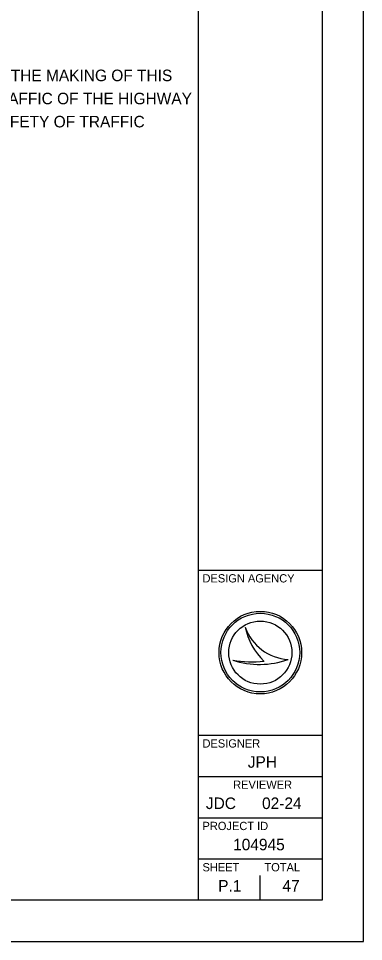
# Model space of a CAD drawing. Extents: x 6.3 to 40.3, y 9 to 31.
# Drawn here: x 36.17 to 40.34, y 9.05 to 20.23 of the extents above; entities that cross this region are included whole.
import ezdxf

# ---------------------------------------------------------------- set-up
doc = ezdxf.new("R2010")
doc.units = 0
for name, color, linetype in [('SH_Border', 7, 'Continuous'), ('SH_Cut_Line', 7, 'Continuous'), ('SH_Data', 7, 'Continuous')]:
    doc.layers.add(name, color=color, linetype=linetype)

msp = doc.modelspace()

# ---------------------------------------------------------------- linework, layer by layer
at = {"layer": 'SH_Border'}
for p, q in [((38.345, 9.546), (38.345, 30.546)), ((38.345, 13.546), (39.845, 13.546)), ((38.345, 11.546), (39.845, 11.546)), ((38.345, 11.046), (39.845, 11.046)), ((38.345, 10.546), (39.845, 10.546)), ((38.345, 10.046), (39.845, 10.046))]:
    msp.add_line(p, q, dxfattribs=at)
msp.add_lwpolyline([(7.845, 30.546), (39.845, 30.546), (39.845, 9.546), (7.845, 9.546)], close=True, dxfattribs=at)
at = {"layer": 'SH_Cut_Line'}
msp.add_lwpolyline([(6.345, 9.046), (40.345, 9.046), (40.345, 31.046), (6.345, 31.046)], close=True, dxfattribs=at)
at = {"layer": 'SH_Data'}
for p, q in [((38.912, 12.855), (38.912, 12.855)), ((39.095, 12.546), (39.095, 12.546)), ((38.762, 12.455), (38.762, 12.455)), ((39.432, 12.464), (39.432, 12.464)), ((39.095, 9.546), (39.095, 9.846)), ((38.72, 9.721), (38.72, 9.721))]:
    msp.add_line(p, q, dxfattribs=at)
for radius in [0.5, 0.477, 0.477, 0.382]:
    msp.add_circle((39.095, 12.546), radius, dxfattribs=at)
for centre, radius, start, end in [((39.461, 13.043), 0.58, 198.9257, 198.9319), ((39.691, 13.016), 0.796, 191.6379, 191.6421), ((39.461, 13.043), 0.58, 198.9319, 267.1657), ((39.691, 13.016), 0.796, 191.6421, 226.0947), ((39.084, 13.416), 1.013, 251.4576, 290.0832), ((38.993, 13.7), 1.266, 259.4964, 259.4995), ((39.084, 13.416), 1.013, 251.4527, 251.4576), ((38.993, 13.7), 1.266, 259.4995, 276.6672)]:
    msp.add_arc(centre, radius, start, end, dxfattribs=at)

# ---------------------------------------------------------------- texts
for s, height, p in [(' I HEREBY APPROVE THESE PLANS AND DECLARE THAT THE MAKING OF THIS', 0.14, (30.872, 19.469)), ('IMPROVEMENT WILL NOT REQUIRE THE CLOSING TO TRAFFIC OF THE HIGHWAY', 0.14, (30.872, 19.189)), ('AND THAT PROVISIONS FOR THE MAINTENANCE AND SAFETY OF TRAFFIC', 0.14, (30.872, 18.909)), ('DESIGN AGENCY', 0.1, (38.395, 13.396)), ('DESIGNER', 0.1, (38.395, 11.396)), ('JPH', 0.14, (38.943, 11.151)), ('REVIEWER', 0.1, (38.766, 10.896)), ('JDC', 0.14, (38.436, 10.651)), ('02-24', 0.14, (39.116, 10.651)), ('PROJECT ID', 0.1, (38.395, 10.396)), ('104945', 0.14, (38.766, 10.151)), ('SHEET', 0.1, (38.395, 9.896)), ('TOTAL', 0.1, (39.145, 9.896)), ('P.1', 0.14, (38.585, 9.651)), ('47', 0.14, (39.363, 9.651))]:
    msp.add_text(s, height=height, dxfattribs=at).set_placement(p)

doc.saveas('drawing.dxf')
